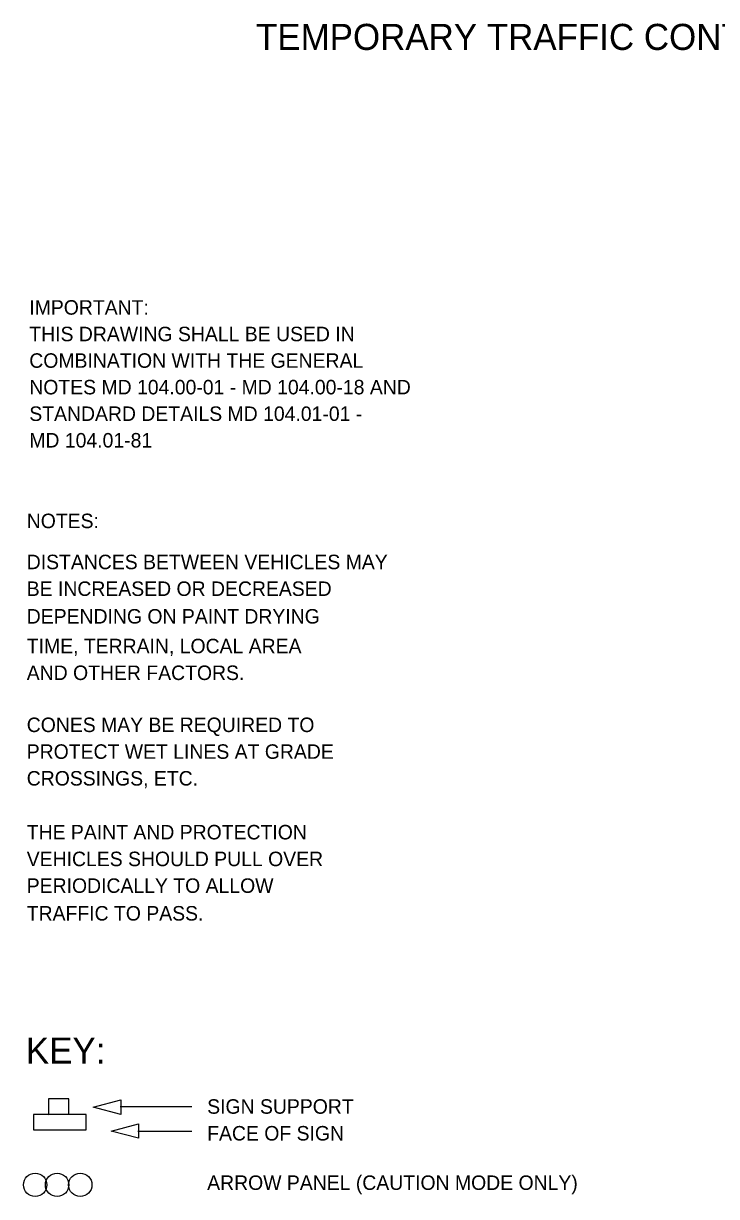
# Model space of a CAD drawing. Extents: x 1531.94 to 1538.58, y 1529.59 to 1539.32.
# Drawn here: x 1531.963 to 1534.83, y 1534.464 to 1539.32 of the extents above; entities that cross this region are included whole.
import ezdxf

# ---------------------------------------------------------------- set-up
doc = ezdxf.new("R2010")
doc.units = 0
for name, color, linetype in [('DETL-DIMS', 7, 'Continuous'), ('DETL-LINE', 7, 'Continuous'), ('DETL-NOTE', 7, 'Continuous'), ('DETL-TITL', 7, 'Continuous'), ('USER-BORD', 7, 'Continuous')]:
    doc.layers.add(name, color=color, linetype=linetype)

# ---------------------------------------------------------------- blocks, each defined once
blk = doc.blocks.new('SIGN13')
at = {"layer": 'USER-BORD'}
for points in [[(-0.0134, 0.0182), (0.011, 0.0189), (0.011, 0.0371), (-0.0134, 0.0371)], [(-0.0314, 0.0182), (-0.0314, 0), (0.032, 0), (0.032, 0.0182)]]:
    blk.add_lwpolyline(points, close=True, dxfattribs=at)

msp = doc.modelspace()

# ---------------------------------------------------------------- linework, layer by layer
at = {"layer": 'DETL-DIMS'}
for p, q in [((1532.3622, 1534.8368), (1532.66, 1534.8368)), ((1532.4352, 1534.7349), (1532.66, 1534.7349))]:
    msp.add_line(p, q, dxfattribs=at)
for points in [[(1532.2512, 1534.8333), (1532.365, 1534.8635), (1532.365, 1534.8032)], [(1532.3255, 1534.7349), (1532.4393, 1534.765), (1532.4393, 1534.7047)]]:
    msp.add_lwpolyline(points, close=True, dxfattribs=at)
at = {"layer": 'DETL-LINE'}
for centre in [(1532.0111, 1534.5122), (1532.1017, 1534.5122), (1532.1978, 1534.5122)]:
    msp.add_circle(centre, 0.0484, dxfattribs=at)

# ---------------------------------------------------------------- block references
at = {"layer": 'DETL-LINE', "xscale": 3.4385190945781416, "yscale": 3.438519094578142}
msp.add_blockref('SIGN13', (1532.1122, 1534.7401), dxfattribs=at)

# ---------------------------------------------------------------- texts
at = {"layer": 'DETL-NOTE'}
for s, p in [('IMPORTANT:', (1531.9868, 1538.1148)), ('THIS DRAWING SHALL BE USED IN', (1531.9868, 1538.0048)), ('COMBINATION WITH THE GENERAL', (1531.9868, 1537.8948)), ('NOTES MD 104.00-01 - MD 104.00-18 AND', (1531.9868, 1537.7848)), ('STANDARD DETAILS MD 104.01-01 -', (1531.9868, 1537.6748)), ('MD 104.01-81', (1531.9868, 1537.5648)), ('NOTES:', (1531.9762, 1537.2309)), ('DISTANCES BETWEEN VEHICLES MAY', (1531.9762, 1537.061)), ('BE INCREASED OR DECREASED', (1531.9762, 1536.9503)), ('DEPENDING ON PAINT DRYING', (1531.9762, 1536.8359)), ('TIME, TERRAIN, LOCAL AREA', (1531.9762, 1536.7129)), ('AND OTHER FACTORS.', (1531.9762, 1536.6022)), ('CONES MAY BE REQUIRED TO ', (1531.9762, 1536.3867)), ('PROTECT WET LINES AT GRADE', (1531.9762, 1536.2759)), ('CROSSINGS, ETC.', (1531.9762, 1536.1653)), ('THE PAINT AND PROTECTION', (1531.9762, 1535.9423)), ('VEHICLES SHOULD PULL OVER', (1531.9762, 1535.8315)), ('PERIODICALLY TO ALLOW ', (1531.9762, 1535.7209)), ('TRAFFIC TO PASS.', (1531.9762, 1535.6064)), ('SIGN SUPPORT', (1532.7228, 1534.8065)), ('FACE OF SIGN', (1532.7228, 1534.6957)), ('ARROW PANEL (CAUTION MODE ONLY)', (1532.7228, 1534.4911))]:
    msp.add_text(s, height=0.06, dxfattribs=at).set_placement(p)
at = {"layer": 'DETL-TITL'}
for s, p in [('TEMPORARY TRAFFIC CONTROL TYPICAL APPLICATION', (1532.925, 1539.2108)), ('KEY:', (1531.9726, 1535.0141))]:
    msp.add_text(s, height=0.108, dxfattribs=at).set_placement(p)

doc.saveas('drawing.dxf')
